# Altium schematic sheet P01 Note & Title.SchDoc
size 297 x 209 mm
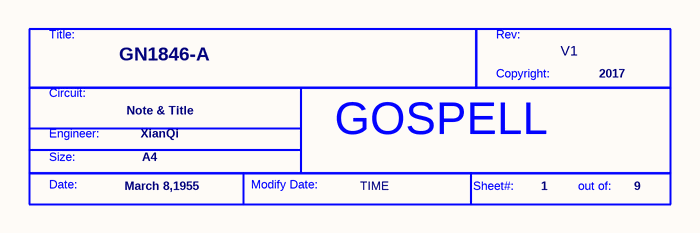
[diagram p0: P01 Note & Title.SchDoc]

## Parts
*  Doc: Note & Title  Page Count: 9  Page Number: 1  Page Create Date: March 8,1955  Page Size: A4  RevCode: V1  Title: GN1846-A  Copyright: 2017  Engineer: XianQi  Page Modify Date: TIME  (hidden comment: GOSPELL)  (graphical)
